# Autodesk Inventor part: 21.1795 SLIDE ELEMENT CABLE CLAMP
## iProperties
Created: 2007-05
Part Number: 21.1795 SLIDE ELEMENT CABLE CLAMP
Document SubType Name: Modeling
Designer: Andy Moles
Material: Steel
Density: 7.85 g/cm^3
Author: Andy Moles
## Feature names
1. Extrusion1
2. Hole1
3. Extrusion2
4. Extrusion3
